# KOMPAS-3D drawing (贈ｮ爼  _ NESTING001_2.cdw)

Views: Вид 1, Слева
Referenced files in E:\+МИША\Скворечник\: Сборка с прямым разрезом.a3d, Дно.m3d, передняя стенка.m3d, Боковая стенка.m3d, Потолок.m3d, Крыша.m3d
Referenced files in \\Smallatom\скворечник\: скворечник _ NESTING001.cdw
Referenced files in C:\Program Files (x86)\ASCON\KOMPAS-3D V13\Libs\PartLib\DATA\VAULT\Methods\kompas\3d\: PLib_Screw_Shurup_900.m3d
Referenced files in C:\Program Files\ASCON\KOMPAS-3D V13\Libs\PartLib\DATA\VAULT\Methods\kompas\3d\: PLib_Screw_Shurup_900.m3d
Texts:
  NESTING001
  скворечник
  Шуруп 3-4 x 40.3 ГОСТ 1145-80
  Шуруп
  ГОСТ
  Л63 ГОСТ 15527-70
  Шуруп 3-4 x 40.3.0115 ГОСТ 1145-80
  Шуруп 3-4x40.3.0115 ГОСТ 1145-80
  Лит-Масса-Масштаб
  Материал-Предприятие
  Title Specification
  Body Specification ( left align )
  Body Specificaton ( centered )
  Поз.
  Кол.
  Приме-
  чание
  Таблица спецификации
  Обозначение стандарта
  Типоразмер
  NESTING001-
  Демьянова Л.В.
  КЮТ СО РАН
  Шуруп 3-4x40.3 ГОСТ 1145-80
  Шуруп 3-4x30.3 ГОСТ 1145-80
Dimensions and other numbers on the sheet: 240; 265; 30; 160; 1; 80; 3; 4; 5; 6; 1:2; 2,41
